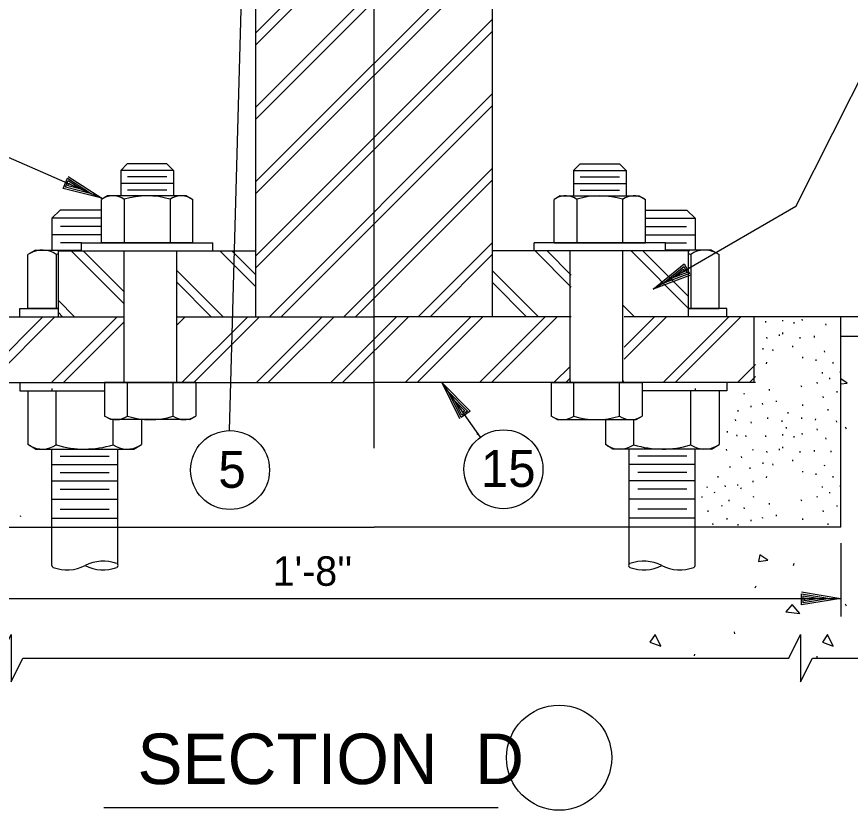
# Model space of a CAD drawing. Extents: x -0.2 to 13.5, y -0.2 to 9.5.
# Drawn here: x 10.768 to 12.088, y 3.055 to 4.312 of the extents above; entities that cross this region are included whole.
import ezdxf

# ---------------------------------------------------------------- set-up
doc = ezdxf.new("R2010")
doc.units = 0
for name, color, linetype in [('Level 10', 7, 'Continuous'), ('Level 13', 7, 'Continuous'), ('Level 2', 7, 'Continuous'), ('Level 3', 7, 'Continuous'), ('Level 50', 7, 'Continuous')]:
    doc.layers.add(name, color=color, linetype=linetype)

msp = doc.modelspace()

# ---------------------------------------------------------------- linework, layer by layer
at = {"layer": 'Level 10'}
for p, q in [((12.0819, 3.659), (12.0802, 3.6623)), ((11.9983, 3.443), (11.9989, 3.4466)), ((11.9374, 3.4076), (11.9392, 3.4108)), ((12.0819, 3.3784), (12.0802, 3.3817)), ((11.9049, 3.3348), (11.9046, 3.3379)), ((11.8413, 3.2998), (11.8418, 3.3026)), ((12.0358, 3.2953), (12.0358, 3.2991))]:
    msp.add_line(p, q, dxfattribs=at)
for points in [[(12.0831, 3.732), (12.0732, 3.7386)], [(12.0732, 3.7308), (12.0831, 3.732)]]:
    msp.add_lwpolyline(points, dxfattribs=at)
for points in [[(11.9424, 3.4495), (11.9576, 3.4515), (11.9448, 3.46)], [(12.0082, 3.3671), (11.9959, 3.3814), (11.9859, 3.3696)], [(11.7706, 3.3216), (11.7877, 3.315), (11.7787, 3.3334)], [(12.0439, 3.3216), (12.061, 3.315), (12.052, 3.3334)]]:
    msp.add_lwpolyline(points, close=True, dxfattribs=at)
at = {"layer": 'Level 13'}
for points in [[(10.74, 3.2959), (10.7587, 3.3334), (10.7587, 3.2585), (10.7774, 3.2959)], [(11.9907, 3.2959), (12.0093, 3.3334), (12.0093, 3.2585), (12.0281, 3.2959)]]:
    msp.add_lwpolyline(points, dxfattribs=at)
at = {"layer": 'Level 2'}
for p, q in [((11.3337, 3.6287), (11.3337, 6.1351)), ((11.1462, 3.8371), (11.1462, 4.9517)), ((11.5212, 3.8371), (11.5212, 4.9517)), ((10.9323, 4.0689), (10.9428, 4.0793)), ((10.9323, 4.0689), (10.9323, 4.0284)), ((11.016, 4.0689), (10.9323, 4.0689)), ((11.0055, 4.0793), (10.9428, 4.0793)), ((11.016, 4.0689), (11.0055, 4.0793)), ((11.016, 4.0689), (11.016, 4.0284)), ((11.6494, 4.0689), (11.6599, 4.0793)), ((11.6494, 4.0689), (11.7331, 4.0689)), ((11.6494, 4.0689), (11.6494, 4.0284)), ((11.6599, 4.0793), (11.7226, 4.0793)), ((11.7331, 4.0689), (11.7226, 4.0793)), ((11.7331, 4.0689), (11.7331, 4.0284)), ((11.0054, 4.0584), (10.9432, 4.0584)), ((11.66, 4.0584), (11.7222, 4.0584)), ((11.016, 4.0479), (10.9323, 4.0479)), ((11.6494, 4.0479), (11.7331, 4.0479)), ((10.9116, 4.0284), (10.902, 4.0228)), ((11.0367, 4.0284), (10.9116, 4.0284)), ((11.0054, 4.0375), (10.9432, 4.0375)), ((11.0367, 4.0284), (11.0464, 4.0228)), ((11.6287, 4.0284), (11.619, 4.0228)), ((11.6287, 4.0284), (11.7538, 4.0284)), ((11.66, 4.0375), (11.7222, 4.0375)), ((11.7538, 4.0284), (11.7635, 4.0228)), ((10.902, 3.9543), (10.902, 4.0228)), ((10.938, 4.023), (10.938, 3.9543)), ((11.0104, 4.023), (11.0104, 3.9543)), ((11.0464, 3.9543), (11.0464, 4.0228)), ((11.619, 3.9543), (11.619, 4.0228)), ((11.6551, 4.023), (11.6551, 3.9543)), ((11.7274, 4.023), (11.7274, 3.9543)), ((11.7635, 3.9543), (11.7635, 4.0228)), ((10.8232, 3.9929), (10.8362, 4.006)), ((10.902, 4.006), (10.8362, 4.006)), ((11.7635, 4.006), (11.8292, 4.006)), ((11.8423, 3.9929), (11.8292, 4.006)), ((10.8232, 3.9929), (10.8232, 3.9425)), ((10.902, 3.9929), (10.8232, 3.9929)), ((11.7635, 3.9929), (11.8423, 3.9929)), ((11.8423, 3.9929), (11.8423, 3.9425)), ((10.902, 3.9799), (10.8367, 3.9799)), ((11.7635, 3.9799), (11.8287, 3.9799)), ((10.902, 3.9669), (10.8232, 3.9669)), ((11.7635, 3.9669), (11.8423, 3.9669)), ((10.87, 3.9539), (10.8367, 3.9539)), ((10.87, 3.9412), (10.87, 3.9543)), ((10.87, 3.9543), (11.0783, 3.9543)), ((11.0464, 3.9543), (10.902, 3.9543)), ((11.0098, 3.9543), (11.0464, 3.9543)), ((11.0783, 3.9412), (11.0783, 3.9543)), ((11.5871, 3.9412), (11.5871, 3.9543)), ((11.7954, 3.9543), (11.5871, 3.9543)), ((11.619, 3.9543), (11.7635, 3.9543)), ((11.6556, 3.9543), (11.619, 3.9543)), ((11.7954, 3.9412), (11.7954, 3.9543)), ((11.7954, 3.9539), (11.8287, 3.9539)), ((10.7974, 3.9425), (10.7853, 3.9356)), ((10.7853, 3.8501), (10.7853, 3.9356)), ((10.7974, 3.9425), (10.87, 3.9425)), ((10.8302, 3.9357), (10.8302, 3.8501)), ((10.8337, 3.9412), (11.1462, 3.9412)), ((10.8337, 3.8371), (10.8337, 3.9412)), ((10.9376, 3.7329), (10.9376, 3.9412)), ((11.0213, 3.7329), (11.0213, 3.9412)), ((11.8337, 3.9412), (11.5212, 3.9412)), ((11.6441, 3.7329), (11.6441, 3.9412)), ((11.7278, 3.7329), (11.7278, 3.9412)), ((11.8681, 3.9425), (11.7954, 3.9425)), ((11.8318, 3.8371), (11.8318, 3.9412)), ((11.8352, 3.9357), (11.8352, 3.8501)), ((11.8681, 3.9425), (11.8801, 3.9356)), ((11.8801, 3.8501), (11.8801, 3.9356)), ((10.7727, 3.8501), (10.8337, 3.8501)), ((10.7727, 3.8371), (10.7727, 3.8501)), ((10.8337, 3.8501), (10.7853, 3.8501)), ((11.8927, 3.8501), (11.8318, 3.8501)), ((11.8318, 3.8501), (11.8801, 3.8501)), ((11.8927, 3.8371), (11.8927, 3.8501)), ((10.4066, 3.8371), (10.9376, 3.8371)), ((11.0213, 3.8371), (11.3337, 3.8371)), ((11.646, 3.8371), (11.3337, 3.8371)), ((12.0732, 3.8371), (11.7297, 3.8371)), ((11.9359, 3.7329), (11.9359, 3.8371)), ((12.0732, 3.5037), (12.0732, 3.8371)), ((12.7399, 3.8371), (12.0732, 3.8371)), ((12.7399, 3.8058), (12.0732, 3.8058)), ((10.7295, 3.7329), (11.3337, 3.7329)), ((10.7727, 3.7329), (10.7727, 3.7199)), ((11.0513, 3.7326), (10.9068, 3.7326)), ((10.9068, 3.7326), (10.9068, 3.6797)), ((10.9373, 3.7353), (10.9373, 3.7326)), ((10.9429, 3.6796), (10.9429, 3.7326)), ((11.0148, 3.7326), (11.0513, 3.7326)), ((11.0153, 3.6796), (11.0153, 3.7326)), ((11.0209, 3.7353), (11.0209, 3.7326)), ((11.0513, 3.7326), (11.0513, 3.6797)), ((11.9378, 3.7329), (11.3337, 3.7329)), ((11.6141, 3.7326), (11.7586, 3.7326)), ((11.6507, 3.7326), (11.6141, 3.7326)), ((11.6141, 3.7326), (11.6141, 3.6797)), ((11.6445, 3.7353), (11.6445, 3.7326)), ((11.6502, 3.6796), (11.6502, 3.7326)), ((11.7225, 3.6796), (11.7225, 3.7326)), ((11.7282, 3.7353), (11.7282, 3.7326)), ((11.7586, 3.7326), (11.7586, 3.6797)), ((11.8927, 3.7329), (11.8927, 3.7199)), ((10.7727, 3.7199), (10.9068, 3.7199)), ((10.7853, 3.7199), (10.7853, 3.6344)), ((10.8232, 3.7232), (10.8232, 3.7199)), ((10.8302, 3.6342), (10.8302, 3.7199)), ((11.8927, 3.7199), (11.7586, 3.7199)), ((11.8352, 3.6342), (11.8352, 3.7199)), ((11.8422, 3.7232), (11.8422, 3.7199)), ((11.8801, 3.7199), (11.8801, 3.6344)), ((10.9165, 3.6741), (10.9068, 3.6797)), ((11.0416, 3.6741), (10.9165, 3.6741)), ((10.9204, 3.6342), (10.9204, 3.6741)), ((10.9653, 3.6741), (10.9653, 3.6344)), ((11.0416, 3.6741), (11.0513, 3.6797)), ((11.6238, 3.6741), (11.6141, 3.6797)), ((11.6238, 3.6741), (11.7489, 3.6741)), ((11.7001, 3.6741), (11.7001, 3.6344)), ((11.745, 3.6342), (11.745, 3.6741)), ((11.7489, 3.6741), (11.7586, 3.6797)), ((10.7974, 3.6274), (10.7853, 3.6344)), ((10.9533, 3.6274), (10.9653, 3.6344)), ((11.7121, 3.6274), (11.7001, 3.6344)), ((11.8681, 3.6274), (11.8801, 3.6344)), ((10.7974, 3.6274), (10.9533, 3.6274)), ((10.8232, 3.4429), (10.8232, 3.6274)), ((10.9275, 3.4454), (10.9275, 3.6274)), ((11.8681, 3.6274), (11.7121, 3.6274)), ((11.7379, 3.4454), (11.7379, 3.6274)), ((11.8422, 3.4429), (11.8422, 3.6274)), ((10.8364, 3.6161), (10.9139, 3.6161)), ((11.829, 3.6161), (11.7515, 3.6161)), ((10.8232, 3.6031), (10.9275, 3.6031)), ((11.8422, 3.6031), (11.7379, 3.6031)), ((10.8364, 3.5901), (10.9139, 3.5901)), ((11.829, 3.5901), (11.7515, 3.5901)), ((10.8232, 3.577), (10.9275, 3.577)), ((11.8422, 3.577), (11.7379, 3.577)), ((10.8364, 3.564), (10.9139, 3.564)), ((11.829, 3.564), (11.7515, 3.564)), ((10.8232, 3.5481), (10.9275, 3.5481)), ((11.8422, 3.5481), (11.7379, 3.5481)), ((10.8364, 3.5322), (10.9139, 3.5322)), ((11.829, 3.5322), (11.7515, 3.5322)), ((10.8232, 3.5181), (10.9275, 3.5181)), ((11.8422, 3.5181), (11.7379, 3.5181)), ((10.4066, 3.5037), (11.3337, 3.5037)), ((12.0732, 3.5037), (11.3337, 3.5037)), ((10.7774, 3.2959), (11.9907, 3.2959)), ((12.0281, 3.2959), (12.8146, 3.2959))]:
    msp.add_line(p, q, dxfattribs=at)
for points in [[(11.1462, 4.2869), (11.5211, 4.6618)], [(11.1462, 4.268), (11.5211, 4.643)], [(11.1462, 4.169), (11.5212, 4.544)], [(11.1462, 4.1501), (11.5212, 4.5251)], [(11.1462, 4.0511), (11.5212, 4.4261)], [(11.1462, 4.0323), (11.5212, 4.4073)], [(11.1462, 3.9333), (11.5212, 4.3083)], [(11.1462, 3.9144), (11.5212, 4.2894)], [(11.1678, 3.8371), (11.5212, 4.1904)], [(11.1867, 3.8371), (11.5212, 4.1716)], [(11.2856, 3.8371), (11.5212, 4.0726)], [(11.3045, 3.8371), (11.5212, 4.0537)], [(11.4035, 3.8371), (11.5212, 3.9547)], [(10.9376, 3.8575), (10.8539, 3.9412)], [(10.9376, 3.8764), (10.8728, 3.9412)], [(11.1462, 3.8846), (11.0895, 3.9412)], [(11.1462, 3.9034), (11.1083, 3.9412)], [(11.4224, 3.8371), (11.5212, 3.9359)], [(11.646, 3.8841), (11.5888, 3.9412)], [(11.646, 3.9029), (11.6077, 3.9412)], [(11.8318, 3.8503), (11.7408, 3.9412)], [(11.8318, 3.8691), (11.7596, 3.9412)], [(11.0946, 3.8371), (11.0213, 3.9104)], [(11.594, 3.8371), (11.5212, 3.9099)], [(11.0758, 3.8371), (11.0213, 3.8916)], [(11.5751, 3.8371), (11.5212, 3.8911)], [(10.8591, 3.8371), (10.8337, 3.8625)], [(10.8403, 3.8371), (10.8337, 3.8436)], [(11.746, 3.8371), (11.7278, 3.8553)], [(10.7295, 3.7388), (10.8278, 3.8371)], [(10.7295, 3.7576), (10.8089, 3.8371)], [(10.8226, 3.7329), (10.9268, 3.8371)], [(11.0213, 3.8238), (11.0345, 3.8371)], [(11.0294, 3.7329), (11.1335, 3.8371)], [(11.0482, 3.7329), (11.1524, 3.8371)], [(11.1472, 3.7329), (11.2514, 3.8371)], [(11.1661, 3.7329), (11.2702, 3.8371)], [(11.2651, 3.7329), (11.3692, 3.8371)], [(11.2839, 3.7329), (11.3881, 3.8371)], [(11.3829, 3.7329), (11.4871, 3.8371)], [(11.4018, 3.7329), (11.5059, 3.8371)], [(11.5008, 3.7329), (11.6049, 3.8371)], [(11.5196, 3.7329), (11.6238, 3.8371)], [(11.7297, 3.7699), (11.7968, 3.8371)], [(11.7297, 3.7888), (11.778, 3.8371)], [(11.7916, 3.7329), (11.8958, 3.8371)], [(11.8105, 3.7329), (11.9147, 3.8371)], [(10.8415, 3.7329), (10.9376, 3.8291)], [(11.6186, 3.7329), (11.6441, 3.7584)], [(11.9095, 3.7329), (11.9378, 3.7612)], [(11.6375, 3.7329), (11.6441, 3.7395)], [(11.9283, 3.7329), (11.9378, 3.7424)]]:
    msp.add_lwpolyline(points, dxfattribs=at)
for centre, radius, start, end in [((10.9202, 3.9971), 0.0314, 55.489, 120.2876), ((10.9746, 3.903), 0.1255, 73.5034, 106.9816), ((11.0281, 3.9971), 0.0314, 59.7124, 124.511), ((11.6373, 3.9971), 0.0314, 55.489, 120.2876), ((11.6908, 3.903), 0.1255, 73.0184, 106.4966), ((11.7452, 3.9971), 0.0314, 59.7124, 124.511), ((10.8081, 3.9035), 0.0391, 55.489, 120.2876), ((10.8759, 3.7862), 0.1564, 105.6701, 106.9821), ((11.7895, 3.7862), 0.1564, 73.0179, 74.3299), ((11.8574, 3.9035), 0.0391, 59.7124, 124.511), ((10.9251, 3.7054), 0.0314, 239.7124, 304.511), ((10.9795, 3.7996), 0.1255, 253.0184, 286.4966), ((11.033, 3.7054), 0.0314, 235.489, 300.2876), ((11.6324, 3.7054), 0.0314, 239.7124, 304.511), ((11.6859, 3.7996), 0.1255, 253.5034, 286.9816), ((11.7403, 3.7054), 0.0314, 235.489, 300.2876), ((10.8081, 3.6665), 0.0391, 239.7124, 304.511), ((10.8748, 3.7838), 0.1564, 253.5034, 286.9816), ((10.9426, 3.6665), 0.0391, 235.489, 300.2876), ((11.7228, 3.6665), 0.0391, 239.7124, 304.511), ((11.7907, 3.7838), 0.1564, 253.0184, 286.4966), ((11.8573, 3.6665), 0.0391, 235.489, 300.2876), ((10.9044, 3.386), 0.0638, 69.8064, 116.6071), ((11.761, 3.386), 0.0638, 63.3929, 110.1936), ((10.8263, 3.4429), 0.00313, 180, 249.6845), ((10.8473, 3.4998), 0.0638, 249.8081, 296.6071), ((10.9044, 3.4998), 0.0638, 243.3929, 290.1936), ((10.9254, 3.4429), 0.00313, 290.1936, 69.8064), ((11.74, 3.4429), 0.00313, 110.1936, 249.8064), ((11.761, 3.4998), 0.0638, 249.8064, 296.6071), ((11.8181, 3.4998), 0.0638, 243.3929, 290.1919), ((11.8391, 3.4429), 0.00313, 290.3155, 0)]:
    msp.add_arc(centre, radius, start, end, dxfattribs=at)
at = {"layer": 'Level 3'}
for p, q in [((11.1047, 3.6567), (11.1249, 4.3894)), ((12.0017, 4.0115), (12.1487, 4.3036)), ((10.6266, 4.1453), (10.9022, 4.0249)), ((12.0017, 4.0115), (11.776, 3.8809)), ((11.791, 3.8895), (11.791, 3.8895)), ((11.776, 3.8809), (11.776, 3.8809)), ((11.9541, 3.8278), (11.954, 3.8298)), ((11.9813, 3.8298), (11.9811, 3.8318)), ((12.0122, 3.8312), (12.012, 3.8332)), ((11.9993, 3.8264), (11.9991, 3.8285)), ((12.0496, 3.8237), (12.0494, 3.8258)), ((11.9562, 3.8026), (11.956, 3.8047)), ((11.9759, 3.8067), (11.9757, 3.8088)), ((11.9813, 3.8096), (11.9813, 3.8119)), ((12.0088, 3.8026), (12.0086, 3.8047)), ((12.0314, 3.8042), (12.0314, 3.8067)), ((11.9972, 3.789), (11.9971, 3.7911)), ((11.9501, 3.785), (11.9499, 3.787)), ((11.9657, 3.7829), (11.9655, 3.785)), ((12.0475, 3.7809), (12.0474, 3.7829)), ((11.9553, 3.7624), (11.9556, 3.7648)), ((12.0129, 3.7714), (12.0127, 3.7734)), ((12.0339, 3.7673), (12.0338, 3.7693)), ((12.0611, 3.7632), (12.0609, 3.7653)), ((12.0438, 3.7472), (12.044, 3.749)), ((12.0556, 3.738), (12.0555, 3.7401)), ((12.0726, 3.7483), (12.0725, 3.7503)), ((11.5025, 3.6464), (11.4417, 3.7323)), ((11.4417, 3.7323), (11.4417, 3.7323)), ((12.0112, 3.7256), (12.0101, 3.7278)), ((12.036, 3.7313), (12.0358, 3.7333)), ((11.4517, 3.7181), (11.4517, 3.7181)), ((11.9202, 3.7136), (11.92, 3.7156)), ((11.9603, 3.7204), (11.9601, 3.7224)), ((12.0672, 3.717), (12.0671, 3.719)), ((11.9494, 3.698), (11.9492, 3.7)), ((11.9711, 3.702), (11.971, 3.704)), ((12.0129, 3.6959), (12.0127, 3.698)), ((12.0455, 3.7088), (12.0453, 3.7108)), ((11.9106, 3.6871), (11.9105, 3.6891)), ((11.9311, 3.6939), (11.9309, 3.6959)), ((11.9898, 3.6837), (11.9896, 3.6857)), ((12.0529, 3.6884), (12.0528, 3.6905)), ((11.9066, 3.6721), (11.9064, 3.6742)), ((11.9576, 3.6755), (11.9574, 3.6775)), ((11.9803, 3.6703), (11.9803, 3.6728)), ((12.0115, 3.6755), (12.0113, 3.6775)), ((12.033, 3.6732), (12.0333, 3.6751)), ((12.0665, 3.6701), (12.0664, 3.6721)), ((11.9318, 3.6683), (11.9311, 3.6708)), ((11.987, 3.6599), (11.9869, 3.6619)), ((12.036, 3.6572), (12.0358, 3.6592)), ((11.4967, 3.6522), (11.4979, 3.651)), ((11.8937, 3.6538), (11.8935, 3.6558)), ((11.9086, 3.6477), (11.9084, 3.6497)), ((11.9229, 3.647), (11.9227, 3.649)), ((11.9541, 3.647), (11.954, 3.649)), ((11.9813, 3.649), (11.9811, 3.651)), ((11.9993, 3.6456), (11.9991, 3.6477)), ((12.0122, 3.6504), (12.012, 3.6524)), ((12.0496, 3.6429), (12.0494, 3.645)), ((11.8923, 3.6253), (11.8921, 3.6273)), ((11.9343, 3.6251), (11.9336, 3.6269)), ((11.9562, 3.6218), (11.956, 3.6239)), ((11.9759, 3.6259), (11.9757, 3.628)), ((11.9813, 3.6288), (11.9813, 3.6311)), ((12.0088, 3.6218), (12.0086, 3.6239)), ((12.0314, 3.6234), (12.0314, 3.6259)), ((12.0577, 3.6225), (12.0575, 3.6245)), ((11.9161, 3.6137), (11.9159, 3.6157)), ((11.9501, 3.6042), (11.9499, 3.6062)), ((11.9972, 3.6083), (11.9971, 3.6103)), ((11.8974, 3.5984), (11.8984, 3.6004)), ((11.9297, 3.596), (11.9295, 3.598)), ((11.9657, 3.6021), (11.9655, 3.6042)), ((12.0129, 3.5906), (12.0127, 3.5926)), ((12.0475, 3.6001), (12.0474, 3.6021)), ((11.8787, 3.5824), (11.8786, 3.5845)), ((11.9553, 3.5816), (11.9556, 3.584)), ((12.0339, 3.5865), (12.0338, 3.5885)), ((12.0611, 3.5824), (12.0609, 3.5845)), ((11.8614, 3.5664), (11.8616, 3.5683)), ((11.8903, 3.5675), (11.8901, 3.5695)), ((11.91, 3.5695), (11.9098, 3.5715)), ((11.9146, 3.5643), (11.9159, 3.5664)), ((11.9344, 3.575), (11.9343, 3.577)), ((12.0438, 3.5664), (12.044, 3.5683)), ((12.0726, 3.5675), (12.0725, 3.5695)), ((11.8536, 3.5505), (11.8534, 3.5525)), ((11.8733, 3.5573), (11.8731, 3.5593)), ((11.9351, 3.5505), (11.9349, 3.5525)), ((12.036, 3.5505), (12.0358, 3.5525)), ((12.0556, 3.5573), (12.0555, 3.5593)), ((11.8964, 3.545), (11.8962, 3.547)), ((11.9603, 3.5396), (11.9601, 3.5416)), ((12.0112, 3.5448), (12.0101, 3.547)), ((11.8631, 3.528), (11.8629, 3.53)), ((11.8849, 3.5362), (11.8847, 3.5382)), ((11.9202, 3.5328), (11.92, 3.5348)), ((12.0455, 3.528), (12.0453, 3.53)), ((12.0672, 3.5362), (12.0671, 3.5382)), ((10.7739, 3.5198), (10.7737, 3.5218)), ((11.893, 3.5158), (11.8928, 3.5178)), ((11.9311, 3.5131), (11.9309, 3.5151)), ((11.9494, 3.5172), (11.9492, 3.5192)), ((11.9711, 3.5212), (11.971, 3.5233)), ((12.0129, 3.5151), (12.0127, 3.5172)), ((11.8706, 3.5076), (11.8704, 3.5097)), ((11.9106, 3.5063), (11.9105, 3.5083)), ((12.0529, 3.5076), (12.0528, 3.5097)), ((12.0732, 3.4784), (12.0732, 3.3623)), ((10.4066, 3.3908), (12.0732, 3.3908)), ((12.0559, 3.3908), (12.0559, 3.3908)), ((12.0732, 3.3908), (12.0732, 3.3908)), ((10.9054, 3.0595), (11.5301, 3.0595))]:
    msp.add_line(p, q, dxfattribs=at)
for points in [[(11.8351, 3.9031), (11.776, 3.8809), (11.8248, 3.921), (11.8336, 3.9057), (11.791, 3.8895), (11.8242, 3.9168), (11.8298, 3.907), (11.8054, 3.8979), (11.8235, 3.9126), (11.8259, 3.9086), (11.8204, 3.9066)], [(11.4693, 3.6754), (11.4417, 3.7323), (11.4861, 3.6874), (11.4717, 3.6772), (11.4517, 3.7181), (11.4819, 3.6876), (11.4726, 3.6811), (11.4613, 3.7045), (11.4776, 3.6879), (11.4738, 3.6852), (11.4714, 3.6904)], [(11.9897, 3.5038), (11.9896, 3.5049)], [(12.0109, 3.4011), (12.0732, 3.3908), (12.0109, 3.3804), (12.0109, 3.3981), (12.0559, 3.3908), (12.0136, 3.3838), (12.0136, 3.3951), (12.0392, 3.3908), (12.0162, 3.3871), (12.0162, 3.3918), (12.0219, 3.3908)]]:
    msp.add_lwpolyline(points, dxfattribs=at)
for centre, radius in [((11.1055, 3.5942), 0.0625), ((11.5386, 3.5954), 0.0625), ((11.6268, 3.1385), 0.0833)]:
    msp.add_circle(centre, radius, dxfattribs=at)
at = {"layer": 'Level 50'}
for p, q in [((10.8863, 4.0318), (10.8863, 4.0318)), ((10.9022, 4.0249), (10.9022, 4.0249))]:
    msp.add_line(p, q, dxfattribs=at)
msp.add_lwpolyline([(10.8492, 4.0593), (10.9022, 4.0249), (10.8409, 4.0404), (10.848, 4.0565), (10.8863, 4.0318), (10.8447, 4.0423), (10.8492, 4.0527), (10.871, 4.0385), (10.8485, 4.0443), (10.8503, 4.0486), (10.8551, 4.0454)], dxfattribs=at)

# ---------------------------------------------------------------- texts
at = {"layer": 'Level 3'}
for s, height, p in [('5', 0.0583, (11.087, 3.566)), ('15', 0.05833, (11.5028, 3.5675)), ("1'-8''", 0.04667, (11.1731, 3.4108)), ('SECTION  D', 0.08, (10.9589, 3.0967))]:
    msp.add_text(s, height=height, dxfattribs=at).set_placement(p)

doc.saveas('drawing.dxf')
